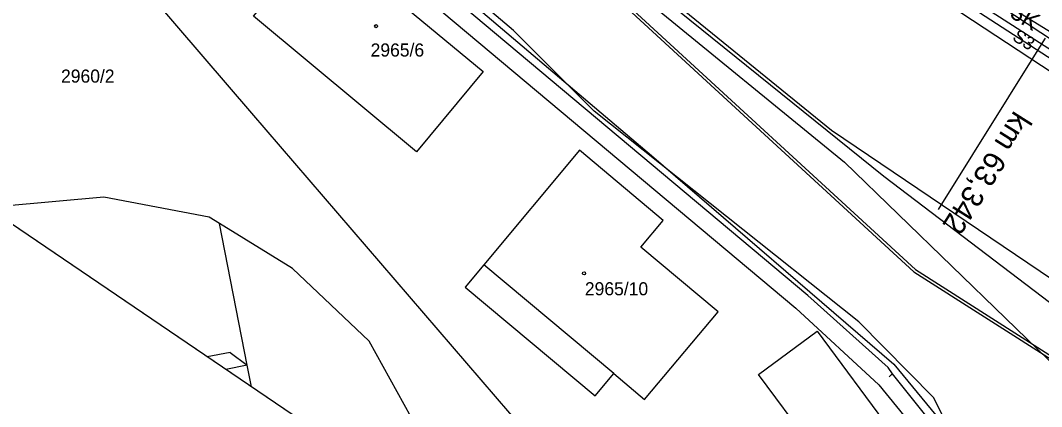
# Model space of a CAD drawing. Extents: x -621145 to -620023, y -1122866 to -1121971.
# Drawn here: x -620461.4 to -620344.4, y -1122701.2 to -1122657 of the extents above; entities that cross this region are included whole.
import ezdxf

# ---------------------------------------------------------------- set-up
doc = ezdxf.new("R2010")
doc.units = 0
for name, color, linetype in [('060601_EOV', 7, 'Continuous'), ('060604_ROZVODY_SEE', 7, 'Continuous'), ('CETIN', 7, 'Continuous'), ('GasNet', 7, 'Continuous'), ('PS 06-14-01_trasa_sdělovací_nové', 7, 'Continuous'), ('RÁMY', 7, 'Continuous'), ('SEE', 7, 'Continuous'), ('SO 06', 7, 'Continuous'), ('SSZT', 7, 'Continuous'), ('SSZT-DK', 7, 'Continuous'), ('VAS vodovod', 7, 'Continuous'), ('Vrstva 1', 7, 'Continuous'), ('Vrstva 27', 7, 'Continuous'), ('Vrstva 53', 7, 'Continuous'), ('Vrstva 55', 7, 'Continuous'), ('Vrstva 56', 7, 'Continuous'), ('Vrstva 57', 7, 'Continuous'), ('Vrstva 6', 7, 'Continuous'), ('ČD-T', 7, 'Continuous')]:
    doc.layers.add(name, color=color, linetype=linetype)

msp = doc.modelspace()

# ---------------------------------------------------------------- linework, layer by layer
at = {"layer": '060601_EOV'}
msp.add_lwpolyline([(-620235.16, -1122712.24), (-620240.17, -1122718.34), (-620243.03, -1122716), (-620248.32, -1122722.77), (-620259.89, -1122713.57), (-620277.71, -1122700.9), (-620282.35, -1122705.3), (-620297.82, -1122689.49), (-620304.22, -1122684.86), (-620310.82, -1122680.06), (-620322.23, -1122672.32), (-620343.18, -1122658.46), (-620368.5, -1122642.9), (-620411.56, -1122614.92), (-620424.16, -1122607.09), (-620443.53, -1122595), (-620456.11, -1122587.12), (-620447.82, -1122572.96), (-620450.95, -1122571.45), (-620470.59, -1122561.48), (-620499.61, -1122545.57), (-620522.04, -1122531.47), (-620538.89, -1122521.21), (-620599.21, -1122483.22)], dxfattribs=at)
at = {"layer": '060604_ROZVODY_SEE'}
msp.add_lwpolyline([(-620243.03, -1122716), (-620248.32, -1122722.77), (-620259.89, -1122713.57), (-620277.71, -1122700.9), (-620282.35, -1122705.3), (-620297.82, -1122689.49), (-620304.22, -1122684.86), (-620310.82, -1122680.06), (-620316.82, -1122675.99), (-620322.23, -1122672.32), (-620326.63, -1122669.41), (-620343.18, -1122658.46), (-620368.5, -1122642.9), (-620411.56, -1122614.92), (-620424.16, -1122607.09), (-620443.53, -1122595), (-620444.24, -1122596.15)], dxfattribs=at)
at = {"layer": 'CETIN'}
msp.add_lwpolyline([(-620402.98, -1122642.16), (-620362.48, -1122674.84), (-620281.95, -1122736.09)], dxfattribs=at)
at = {"layer": 'GasNet'}
msp.add_lwpolyline([(-620545.62, -1122586.36), (-620544.33, -1122585.86), (-620529.1, -1122581.91), (-620527.88, -1122581.68), (-620501.79, -1122593.01), (-620500.52, -1122592.53), (-620484.13, -1122585.56), (-620478.57, -1122583.14), (-620474.2, -1122586.82), (-620449.91, -1122606.86), (-620450.02, -1122607.5), (-620458.5, -1122620.02), (-620458.8, -1122620.62), (-620432.06, -1122640.49), (-620425.64, -1122643.91), (-620417.98, -1122647.99), (-620389.11, -1122672.47), (-620361.34, -1122696.38), (-620351.16, -1122708.72), (-620351, -1122709.02), (-620350.83, -1122709.39), (-620350.53, -1122710.79), (-620349.5, -1122710.44), (-620336.68, -1122702.48)], dxfattribs=at)
at = {"layer": 'PS 06-14-01_trasa_sdělovací_nové'}
msp.add_lwpolyline([(-620248.32, -1122722.77), (-620259.89, -1122713.57), (-620277.71, -1122700.89), (-620282.35, -1122705.3), (-620297.82, -1122689.49), (-620310.82, -1122680.06), (-620322.23, -1122672.32), (-620343.18, -1122658.46), (-620368.5, -1122642.9), (-620411.56, -1122614.92), (-620456.11, -1122587.12), (-620544.95, -1122530.86), (-620538.89, -1122521.21), (-620538.89, -1122521.21), (-620538.89, -1122521.21)], dxfattribs=at)
at = {"layer": 'RÁMY'}
for points in [[(-621061.56, -1122093.92), (-620106.07, -1122742.82), (-620189.51, -1122865.67), (-621144.99, -1122216.77)], [(-620887.83, -1122211.9), (-620106.07, -1122742.82), (-620189.51, -1122865.67), (-620971.26, -1122334.75)]]:
    msp.add_lwpolyline(points, close=True, dxfattribs=at)
at = {"layer": 'SEE'}
msp.add_lwpolyline([(-620244.52, -1122694.3), (-620246.55, -1122692.66), (-620267.47, -1122718.6), (-620268.22, -1122719.53), (-620284.41, -1122704.62), (-620304.33, -1122686.26), (-620309.55, -1122681.45), (-620327.71, -1122669.48), (-620362.83, -1122646.34), (-620390.25, -1122629.02), (-620411.93, -1122614.96), (-620423.13, -1122608.01), (-620468.34, -1122579.91), (-620468.34, -1122579.91), (-620460.94, -1122568.1), (-620517.42, -1122533.03), (-620535, -1122522.48), (-620545.41, -1122539.45), (-620611.37, -1122497.7)], dxfattribs=at)
at = {"layer": 'SO 06'}
msp.add_lwpolyline([(-620298.23, -1122690.95), (-620299.6, -1122691.25), (-620312.94, -1122681.47), (-620333.34, -1122667.92), (-620356.71, -1122652.76), (-620357.2, -1122652.95), (-620412.63, -1122616.6), (-620445.65, -1122595.98), (-620446, -1122596.55)], dxfattribs=at)
at = {"layer": 'SSZT'}
msp.add_lwpolyline([(-620879.24, -1122313.32), (-620842.99, -1122336.61), (-620835.05, -1122343.25), (-620812.66, -1122358.95), (-620764.9, -1122389.75), (-620688.59, -1122438.97), (-620596.98, -1122496.73), (-620576.74, -1122509.48), (-620506.75, -1122556.12), (-620447.29, -1122593.62), (-620363.27, -1122647.56), (-620313.97, -1122679.22), (-620306.51, -1122669.29), (-620273.14, -1122696.27), (-620258.42, -1122709.14), (-620248.07, -1122696.09)], dxfattribs=at)
at = {"layer": 'SSZT-DK'}
msp.add_lwpolyline([(-620617.36, -1122456.74), (-620574.42, -1122482.6), (-620528.16, -1122511.11), (-620496.31, -1122530.83), (-620515.02, -1122558.81), (-620500.38, -1122568.61), (-620465.39, -1122591.45), (-620452.16, -1122605.02), (-620438.23, -1122615.5), (-620392.31, -1122655.21), (-620359.04, -1122685.8), (-620308.77, -1122717.8)], dxfattribs=at)
at = {"layer": 'VAS vodovod'}
for points in [[(-620346.78, -1122722.2), (-620350.17, -1122711.62), (-620361.5, -1122697.5), (-620361.99, -1122696.76), (-620371.19, -1122688.51), (-620418.43, -1122648.88), (-620439.22, -1122636.74), (-620439.29, -1122636.69), (-620439.37, -1122636.64), (-620460.46, -1122621.06), (-620460.7, -1122620.9), (-620459.95, -1122619.77), (-620451.51, -1122607.79), (-620450.89, -1122606.96), (-620476.53, -1122586.08), (-620476.53, -1122586.08), (-620476.87, -1122585.61)], [(-620361.87, -1122697.82), (-620361.59, -1122697.59), (-620361.5, -1122697.5)]]:
    msp.add_lwpolyline(points, dxfattribs=at)
at = {"layer": 'Vrstva 1'}
msp.add_lwpolyline([(-620326.63, -1122669.41), (-620343.18, -1122658.46), (-620368.5, -1122642.9), (-620411.56, -1122614.92), (-620436.76, -1122599.26), (-620456.11, -1122587.12)], dxfattribs=at)
at = {"layer": 'Vrstva 53'}
msp.add_line((-620334.71, -1122668.63), (-620411.71, -1122617.81), dxfattribs=at)
at = {"layer": 'Vrstva 55'}
for p, q in [((-620466.94, -1122589.51), (-620368.46, -1122669.58)), ((-620334.71, -1122668.63), (-620411.71, -1122617.81)), ((-620434.88, -1122667.63), (-620473.14, -1122623.15)), ((-620420.38, -1122629.64), (-620366.98, -1122673.23)), ((-620404.9, -1122658.18), (-620423.22, -1122642.55)), ((-620395.68, -1122667.41), (-620404.9, -1122658.18)), ((-620391.77, -1122717.74), (-620434.88, -1122667.63)), ((-620365.35, -1122691.52), (-620395.68, -1122667.41)), ((-620368.46, -1122669.58), (-620310.57, -1122708.76)), ((-620397.34, -1122671.88), (-620408.32, -1122685)), ((-620387.77, -1122679.92), (-620397.34, -1122671.88)), ((-620366.98, -1122673.23), (-620342.37, -1122697.07)), ((-620451.85, -1122677.25), (-620463.28, -1122678.3)), ((-620439.78, -1122679.56), (-620451.85, -1122677.25)), ((-620438.61, -1122680.28), (-620439.78, -1122679.56)), ((-620390.32, -1122682.97), (-620387.77, -1122679.92)), ((-620435.41, -1122696.52), (-620438.61, -1122680.28)), ((-620430.21, -1122685.42), (-620438.61, -1122680.28)), ((-620381.44, -1122690.4), (-620390.32, -1122682.97)), ((-620421.46, -1122693.76), (-620430.21, -1122685.42)), ((-620408.32, -1122685), (-620410.45, -1122687.55)), ((-620410.45, -1122687.55), (-620395.56, -1122700.01)), ((-620389.88, -1122700.43), (-620381.44, -1122690.4)), ((-620356.78, -1122700.2), (-620365.35, -1122691.52)), ((-620376.85, -1122697.59), (-620370.13, -1122692.59)), ((-620370.13, -1122692.59), (-620349.5, -1122720.4)), ((-620415.57, -1122704.35), (-620421.46, -1122693.76)), ((-620435.41, -1122696.52), (-620437.86, -1122697)), ((-620434.92, -1122699), (-620435.41, -1122696.52)), ((-620395.56, -1122700.01), (-620393.43, -1122697.46)), ((-620393.43, -1122697.46), (-620389.88, -1122700.43)), ((-620347.29, -1122718.92), (-620356.78, -1122700.2))]:
    msp.add_line(p, q, dxfattribs=at)
for points in [[(-620432.38, -1122643.03), (-620419.73, -1122650.41), (-620372.55, -1122689.97), (-620363.06, -1122698.75), (-620352.08, -1122712.18), (-620349.5, -1122720.4)], [(-620434.7, -1122656.53), (-620427.07, -1122647.39), (-620408.37, -1122662.86), (-620416.01, -1122672.06), (-620434.7, -1122656.53)], [(-620377.36, -1122710.19), (-620370.99, -1122705.44), (-620376.85, -1122697.59)]]:
    msp.add_lwpolyline(points, dxfattribs=at)
at = {"layer": 'Vrstva 56'}
for p, q in [((-620393.43, -1122697.46), (-620408.32, -1122685)), ((-620437.36, -1122695.04), (-620439.99, -1122695.56)), ((-620437.36, -1122695.04), (-620435.41, -1122696.52))]:
    msp.add_line(p, q, dxfattribs=at)
at = {"layer": 'Vrstva 57'}
for centre in [(-620420.65, -1122657.67), (-620396.83, -1122685.99)]:
    msp.add_circle(centre, 0.175, dxfattribs=at)
at = {"layer": 'Vrstva 6'}
for p, q in [((-620344.27, -1122659.46), (-620356.26, -1122678.68)), ((-620344, -1122659.04), (-620344.54, -1122659.88))]:
    msp.add_line(p, q, dxfattribs=at)
at = {"layer": 'ČD-T'}
msp.add_lwpolyline([(-620617.18, -1122456.5), (-620574.24, -1122482.37), (-620527.97, -1122510.87), (-620481.08, -1122540.08), (-620497, -1122565.38), (-620499.27, -1122568.98), (-620465.21, -1122591.22), (-620451.97, -1122604.79), (-620438.05, -1122615.26), (-620392.12, -1122654.98), (-620358.85, -1122685.56), (-620308.58, -1122717.56)], dxfattribs=at)

# ---------------------------------------------------------------- texts
at = {"layer": 'Vrstva 27'}
msp.add_text('V3-3K', height=2, rotation=328.4879, dxfattribs=at).set_placement((-620351.73, -1122654.38))
at = {"layer": 'Vrstva 57'}
for s, p in [('2965/6', (-620421.28, -1122661.15)), ('2960/2', (-620456.75, -1122664.14)), ('2965/10', (-620396.73, -1122688.5))]:
    msp.add_text(s, height=1.5, dxfattribs=at).set_placement(p)
at = {"layer": 'Vrstva 6'}
for s, height, rotation, p in [('S3', 1.5, 327.7824, (-620347.86, -1122659.2)), ('km 63,342', 2.5, 237.7824, (-620347.53, -1122667.24))]:
    msp.add_text(s, height=height, rotation=rotation, dxfattribs=at).set_placement(p)

doc.saveas('drawing.dxf')
